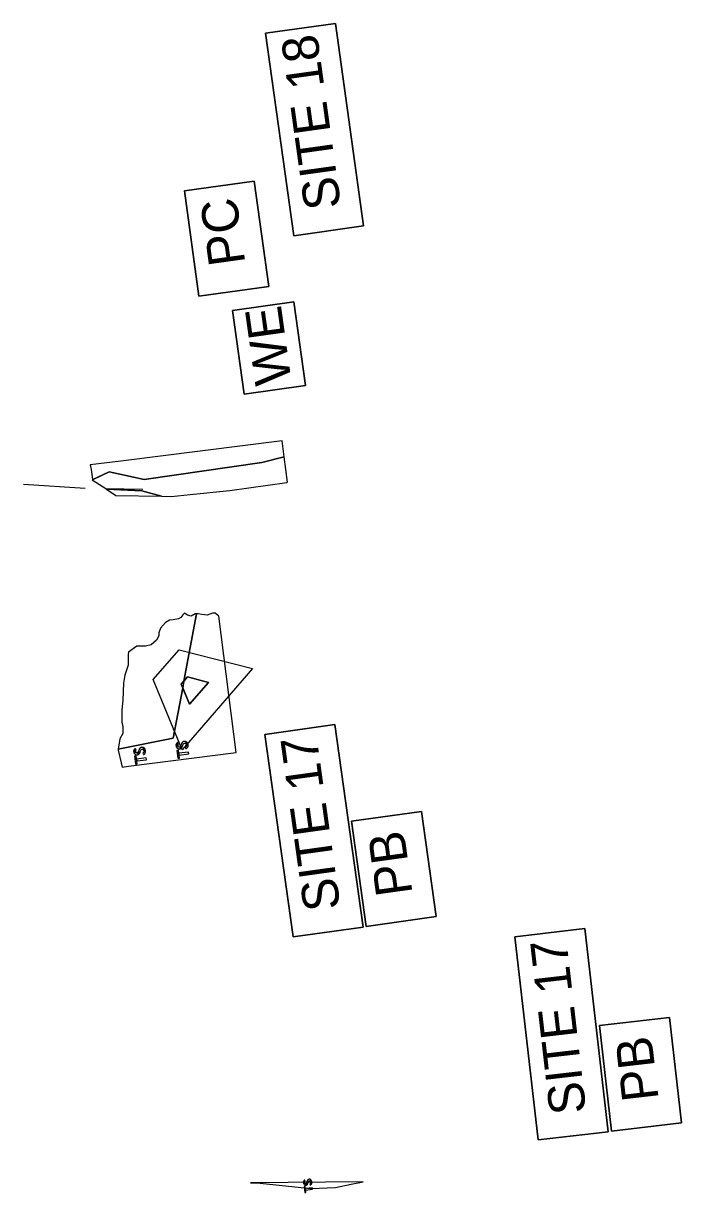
# Model space of a CAD drawing. Extents: x 474218 to 481634, y 484357 to 504997.
# Drawn here: x 478213.3 to 478484.7, y 496625.4 to 497106.9 of the extents above; entities that cross this region are included whole.
import ezdxf

# ---------------------------------------------------------------- set-up
doc = ezdxf.new("R2010")
doc.units = 0
for name, color, linetype in [('Exist Hydro Jurisdictional Stream or Body of Water', 7, 'Continuous'), ('Old_Level_29', 7, 'Continuous'), ('Old_Level_30', 7, 'Continuous'), ('Prop Boundary Clearing Mechanized Hatching CELL', 7, 'Continuous'), ('Prop Earthen Structure Fill In Wetlands Hatching CELL', 7, 'Continuous'), ('Prop Earthen Structure Impacts In Surface Waters Pond Hatching CELL', 7, 'Continuous'), ('Prop Grid Mask', 7, 'Continuous'), ('Scratch_Level_4', 7, 'Continuous'), ('Temp Earthen Structure Impacts In Surface Waters Hatching CELL', 7, 'Continuous')]:
    doc.layers.add(name, color=color, linetype=linetype)

msp = doc.modelspace()

# ---------------------------------------------------------------- linework, layer by layer
at = {"layer": 'Exist Hydro Jurisdictional Stream or Body of Water'}
for points in [[(478285.73, 496994.6), (478279.71, 497037.91), (478308.51, 497041.92), (478314.54, 496998.61)], [(478354.65, 496735.02), (478348.62, 496778.33), (478377.42, 496782.34), (478383.45, 496739.03)], [(478455.76, 496650.73), (478450.76, 496694.17), (478479.65, 496697.5), (478484.66, 496654.06)]]:
    msp.add_lwpolyline(points, close=True, dxfattribs=at)
at = {"layer": 'Old_Level_29'}
for points in [[(478324.77, 497019.47), (478313.16, 497102.9), (478341.97, 497106.91), (478353.58, 497023.48)], [(478324.51, 496730.65), (478312.9, 496814.09), (478341.72, 496818.1), (478353.33, 496734.66)], [(478425.54, 496647.07), (478415.89, 496730.75), (478444.79, 496734.09), (478454.44, 496650.4)]]:
    msp.add_lwpolyline(points, close=True, dxfattribs=at)
at = {"layer": 'Old_Level_30'}
msp.add_lwpolyline([(478304.34, 496954.22), (478299.55, 496988.65), (478324.84, 496992.17), (478329.63, 496957.74)], close=True, dxfattribs=at)
at = {"layer": 'Prop Boundary Clearing Mechanized Hatching CELL'}
for p, q in [((478322.2, 496917.91), (478320.86, 496928.41)), ((478247.68, 496915.04), (478262.17, 496914.35))]:
    msp.add_line(p, q, dxfattribs=at)
for points in [[(478320.86, 496928.41), (478311.66, 496926.12), (478263.19, 496919.03), (478248.75, 496922.25), (478241.67, 496918.9), (478247.68, 496915.04)], [(478282.07, 496912.91), (478298.47, 496914.55), (478321.92, 496917.86), (478322.2, 496917.91)], [(478262.17, 496914.35), (478270.31, 496912.18), (478274.23, 496912.1), (478282.07, 496912.91)]]:
    msp.add_lwpolyline(points, dxfattribs=at)
at = {"layer": 'Prop Earthen Structure Fill In Wetlands Hatching CELL'}
for p, q in [((478262.16, 496914.34), (478247.67, 496915.02)), ((478247.67, 496915.02), (478251.52, 496912.54)), ((478270.31, 496912.18), (478262.16, 496914.34))]:
    msp.add_line(p, q, dxfattribs=at)
msp.add_lwpolyline([(478251.52, 496912.54), (478270.31, 496912.18), (478270.31, 496912.18)], dxfattribs=at)
at = {"layer": 'Prop Earthen Structure Impacts In Surface Waters Pond Hatching CELL'}
for p, q in [((478279.51, 496836.01), (478284.67, 496863.72)), ((478284.67, 496863.72), (478284.22, 496863.68)), ((478279.01, 496833.28), (478279.51, 496836.01)), ((478279.51, 496836.01), (478279.01, 496833.28)), ((478281.03, 496837.75), (478279.51, 496836.01)), ((478289.69, 496835.52), (478281.03, 496837.75)), ((478281.82, 496826.47), (478289.69, 496835.52)), ((478275.15, 496812.55), (478279.01, 496833.28)), ((478279.01, 496833.28), (478281.82, 496826.47)), ((478252.43, 496807.95), (478275.15, 496812.55))]:
    msp.add_line(p, q, dxfattribs=at)
msp.add_lwpolyline([(478284.22, 496863.68), (478282.48, 496862.74), (478280.93, 496863.13), (478279.81, 496863.95), (478279.06, 496863.35), (478278.21, 496862.25), (478277.31, 496861.63), (478275.05, 496861.28), (478273.6, 496861.08), (478271.92, 496860.13), (478269.89, 496857.79), (478269.22, 496855.97), (478269.23, 496854.69), (478268.17, 496852.91), (478265.98, 496850.96), (478263.73, 496850.4), (478261.29, 496850.44), (478260.12, 496850.39), (478256.68, 496847.93), (478256.5, 496846.94), (478256.53, 496842.54), (478255.13, 496838.43), (478254.67, 496835.16), (478254.38, 496828.25), (478253.86, 496824.24), (478253.95, 496819.06), (478254.4, 496817.15), (478254.36, 496814.43), (478253.14, 496812.27), (478252.43, 496807.95)], dxfattribs=at)
at = {"layer": 'Prop Grid Mask'}
for points in [[(478353.58, 497023.48), (478341.97, 497106.91), (478313.16, 497102.9), (478324.77, 497019.47)], [(478314.54, 496998.61), (478308.51, 497041.92), (478279.71, 497037.91), (478285.73, 496994.6)], [(478329.63, 496957.74), (478324.84, 496992.17), (478299.55, 496988.65), (478304.34, 496954.22)], [(478353.33, 496734.66), (478341.72, 496818.1), (478312.9, 496814.09), (478324.51, 496730.65)], [(478383.45, 496739.03), (478377.42, 496782.34), (478348.62, 496778.33), (478354.65, 496735.02)], [(478454.44, 496650.4), (478444.79, 496734.09), (478415.89, 496730.75), (478425.54, 496647.07)], [(478484.66, 496654.06), (478479.65, 496697.5), (478450.76, 496694.17), (478455.76, 496650.73)]]:
    msp.add_lwpolyline(points, close=True, dxfattribs=at)
at = {"layer": 'Scratch_Level_4'}
for p, q in [((478213.34, 496917.2), (478238.77, 496915.45)), ((478247.22, 496915.33), (478262.57, 496915.09)), ((478278.4, 496834.73), (478281.03, 496837.75)), ((478281.03, 496837.75), (478289.69, 496835.52)), ((478289.69, 496835.52), (478281.82, 496826.47)), ((478281.82, 496826.47), (478278.4, 496834.73))]:
    msp.add_line(p, q, dxfattribs=at)
msp.add_lwpolyline([(478278.76, 496807.69), (478266.8, 496836.63), (478277.53, 496848.98), (478307.85, 496841.18)], close=True, dxfattribs=at)
at = {"layer": 'Temp Earthen Structure Impacts In Surface Waters Hatching CELL'}
for p, q in [((478320, 496935.04), (478253.54, 496926.56)), ((478320.85, 496928.41), (478320, 496935.04)), ((478253.54, 496926.56), (478240.89, 496925.1)), ((478241.8, 496919.02), (478241.81, 496918.96)), ((478284.67, 496863.72), (478279.51, 496836.01)), ((478301.11, 496806.61), (478293.95, 496862.73)), ((478279.51, 496836.01), (478281.03, 496837.75)), ((478281.03, 496837.75), (478289.69, 496835.52)), ((478289.69, 496835.52), (478281.82, 496826.47)), ((478279.01, 496833.28), (478275.15, 496812.55)), ((478281.82, 496826.47), (478279.01, 496833.28)), ((478275.15, 496812.55), (478252.43, 496807.95)), ((478256.68, 496800.94), (478301.11, 496806.61)), ((478254.04, 496800.57), (478256.68, 496800.94))]:
    msp.add_line(p, q, dxfattribs=at)
for points in [[(478241.81, 496918.96), (478248.75, 496922.25), (478263.19, 496919.03), (478311.66, 496926.12), (478320.85, 496928.41)], [(478240.89, 496925.1), (478241.22, 496923.15), (478241.8, 496919.02)], [(478293.95, 496862.73), (478292.42, 496864), (478291.24, 496863.98), (478289.14, 496863.15), (478286.92, 496863.45), (478285.38, 496863.78), (478284.67, 496863.72)], [(478252.43, 496807.95), (478252.36, 496807.54), (478253.69, 496802.38), (478254.04, 496800.57)], [(478312.15, 496629.12), (478331.81, 496627.04), (478342.06, 496627.54), (478348.46, 496628.92), (478353.35, 496629.81), (478306.92, 496629.36), (478310.93, 496629.25), (478312.15, 496629.12)]]:
    msp.add_lwpolyline(points, dxfattribs=at)
for points in [[(478259, 496806.4), (478259.02, 496806.34), (478258.88, 496807.5), (478258.88, 496807.48), (478258.86, 496806.89), (478258.86, 496806.89)], [(478260.43, 496805.68), (478260.6, 496805.71), (478260.5, 496806.59), (478260.34, 496806.47), (478260.08, 496806.43), (478260.07, 496806.42), (478260, 496806.44), (478259.83, 496806.49), (478259.76, 496806.55), (478259.67, 496806.63), (478259.63, 496806.67), (478259.62, 496806.7), (478259.58, 496806.81), (478259.52, 496806.96), (478259.37, 496808.25), (478259.29, 496808.21), (478259.09, 496807.97), (478259.04, 496807.92), (478258.88, 496807.5), (478259.02, 496806.34), (478259.26, 496806.02), (478259.32, 496805.93), (478259.57, 496805.79), (478259.66, 496805.74), (478259.7, 496805.71), (478259.74, 496805.7), (478259.74, 496805.69), (478259.78, 496805.69), (478259.86, 496805.68), (478259.92, 496805.67), (478260.1, 496805.64), (478260.16, 496805.63), (478260.18, 496805.63)], [(478259.7, 496807.61), (478259.85, 496807.77), (478259.64, 496808.07), (478259.57, 496808.18), (478259.48, 496808.32), (478259.44, 496808.3), (478259.44, 496808.29), (478259.41, 496808.28), (478259.37, 496808.25), (478259.52, 496806.96), (478259.52, 496807.29), (478259.55, 496807.35), (478259.55, 496807.36), (478259.58, 496807.42), (478259.65, 496807.56)], [(478260.87, 496805.88), (478260.96, 496805.94), (478260.82, 496807.18), (478260.74, 496806.95), (478260.57, 496806.65), (478260.5, 496806.6), (478260.6, 496805.71), (478260.68, 496805.76)], [(478262.97, 496807.63), (478263.05, 496807.35), (478262.9, 496808.65), (478262.85, 496808.68), (478262.84, 496808.68), (478262.83, 496808.68), (478262.73, 496808.73), (478262.69, 496808.74), (478262.66, 496808.74), (478262.52, 496808.75), (478262.46, 496808.76), (478262.42, 496808.76), (478262.23, 496808.78), (478262.13, 496808.76), (478261.87, 496808.7), (478261.75, 496808.67), (478261.67, 496808.61), (478261.5, 496808.49), (478261.5, 496808.49), (478261.37, 496808.39), (478261.29, 496808.27), (478261.1, 496807.95), (478261.06, 496807.85), (478260.89, 496807.41), (478260.82, 496807.18), (478260.96, 496805.94), (478261.05, 496806.04), (478261.24, 496806.28), (478261.28, 496806.37), (478261.46, 496806.78), (478261.53, 496806.98), (478261.64, 496807.28), (478261.78, 496807.65), (478261.86, 496807.75), (478261.96, 496807.88), (478262.21, 496807.99), (478262.32, 496807.99), (478262.5, 496807.99), (478262.55, 496807.97), (478262.62, 496807.95), (478262.76, 496807.89), (478262.79, 496807.85), (478262.84, 496807.8), (478262.95, 496807.67), (478262.96, 496807.65)], [(478263.72, 496806.74), (478263.75, 496807.39), (478263.57, 496808.04), (478263.57, 496808.04), (478263.23, 496808.46), (478263.19, 496808.51), (478262.9, 496808.65), (478263.05, 496807.35), (478263.04, 496806.99), (478263.04, 496806.99), (478263.03, 496806.96), (478262.96, 496806.77), (478262.93, 496806.7), (478262.9, 496806.67), (478262.78, 496806.54), (478262.72, 496806.49), (478262.68, 496806.46), (478262.52, 496806.38), (478262.73, 496806.02), (478262.79, 496805.93), (478262.86, 496805.81), (478262.99, 496805.87), (478263.02, 496805.88), (478263.06, 496805.89), (478263.15, 496805.94), (478263.16, 496805.95), (478263.16, 496805.95), (478263.21, 496805.99), (478263.45, 496806.21), (478263.48, 496806.24), (478263.72, 496806.73)], [(478276.48, 496808.83), (478276.5, 496808.77), (478276.36, 496809.93), (478276.36, 496809.91), (478276.34, 496809.33), (478276.34, 496809.32)], [(478277.91, 496808.11), (478278.08, 496808.15), (478277.98, 496809.03), (478277.82, 496808.91), (478277.56, 496808.86), (478277.55, 496808.86), (478277.48, 496808.87), (478277.31, 496808.92), (478277.24, 496808.98), (478277.15, 496809.06), (478277.11, 496809.1), (478277.1, 496809.13), (478277.06, 496809.25), (478277, 496809.39), (478276.85, 496810.69), (478276.77, 496810.64), (478276.57, 496810.4), (478276.52, 496810.35), (478276.36, 496809.93), (478276.5, 496808.77), (478276.74, 496808.45), (478276.8, 496808.37), (478277.05, 496808.22), (478277.14, 496808.17), (478277.18, 496808.15), (478277.21, 496808.13), (478277.22, 496808.13), (478277.26, 496808.12), (478277.34, 496808.11), (478277.4, 496808.1), (478277.57, 496808.08), (478277.64, 496808.07), (478277.66, 496808.06)], [(478277.03, 496804.28), (478277.68, 496804.35), (478277.31, 496807.57), (478276.66, 496807.5)], [(478277.18, 496810.04), (478277.33, 496810.2), (478277.12, 496810.51), (478277.05, 496810.61), (478276.96, 496810.75), (478276.92, 496810.73), (478276.92, 496810.73), (478276.89, 496810.71), (478276.85, 496810.69), (478277, 496809.39), (478277, 496809.73), (478277.02, 496809.78), (478277.03, 496809.79), (478277.06, 496809.86), (478277.12, 496809.99)], [(478277.54, 496805.58), (478281.54, 496806.05), (478281.45, 496806.8), (478277.45, 496806.34)], [(478278.35, 496808.31), (478278.44, 496808.37), (478278.3, 496809.61), (478278.22, 496809.38), (478278.05, 496809.08), (478277.98, 496809.03), (478278.08, 496808.14), (478278.16, 496808.19)], [(478280.45, 496810.07), (478280.53, 496809.78), (478280.38, 496811.08), (478280.33, 496811.11), (478280.32, 496811.11), (478280.31, 496811.12), (478280.21, 496811.17), (478280.17, 496811.17), (478280.14, 496811.17), (478280, 496811.19), (478279.94, 496811.19), (478279.89, 496811.2), (478279.71, 496811.21), (478279.61, 496811.19), (478279.35, 496811.13), (478279.23, 496811.11), (478279.15, 496811.04), (478278.98, 496810.92), (478278.98, 496810.92), (478278.85, 496810.83), (478278.77, 496810.7), (478278.58, 496810.38), (478278.54, 496810.28), (478278.37, 496809.84), (478278.3, 496809.61), (478278.44, 496808.37), (478278.53, 496808.48), (478278.72, 496808.72), (478278.76, 496808.81), (478278.94, 496809.22), (478279.01, 496809.41), (478279.12, 496809.72), (478279.26, 496810.08), (478279.34, 496810.18), (478279.44, 496810.31), (478279.69, 496810.42), (478279.8, 496810.42), (478279.98, 496810.43), (478280.03, 496810.41), (478280.1, 496810.38), (478280.24, 496810.33), (478280.27, 496810.29), (478280.32, 496810.23), (478280.43, 496810.1), (478280.44, 496810.08)], [(478281.2, 496809.18), (478281.23, 496809.83), (478281.05, 496810.47), (478281.05, 496810.48), (478280.71, 496810.89), (478280.67, 496810.94), (478280.38, 496811.08), (478280.53, 496809.78), (478280.52, 496809.42), (478280.52, 496809.42), (478280.51, 496809.39), (478280.44, 496809.2), (478280.41, 496809.13), (478280.38, 496809.1), (478280.26, 496808.97), (478280.2, 496808.92), (478280.16, 496808.9), (478279.99, 496808.81), (478280.21, 496808.45), (478280.27, 496808.36), (478280.34, 496808.24), (478280.47, 496808.3), (478280.5, 496808.31), (478280.54, 496808.33), (478280.63, 496808.37), (478280.64, 496808.38), (478280.64, 496808.38), (478280.69, 496808.42), (478280.93, 496808.64), (478280.96, 496808.67), (478281.2, 496809.17)], [(478259.55, 496801.84), (478260.2, 496801.92), (478259.83, 496805.14), (478259.18, 496805.06)], [(478260.06, 496803.15), (478264.06, 496803.61), (478263.97, 496804.37), (478259.97, 496803.91)], [(478328.91, 496629.02), (478328.92, 496628.98), (478328.81, 496629.9), (478328.81, 496629.89), (478328.8, 496629.42), (478328.8, 496629.42)], [(478329.93, 496628.43), (478330.05, 496628.46), (478329.97, 496629.16), (478329.86, 496629.07), (478329.67, 496629.03), (478329.66, 496629.03), (478329.62, 496629.05), (478329.49, 496629.08), (478329.44, 496629.13), (478329.38, 496629.2), (478329.35, 496629.23), (478329.34, 496629.26), (478329.31, 496629.35), (478329.27, 496629.47), (478329.15, 496630.5), (478329.1, 496630.47), (478328.95, 496630.28), (478328.92, 496630.24), (478328.81, 496629.9), (478328.92, 496628.98), (478329.09, 496628.72), (478329.14, 496628.65), (478329.32, 496628.53), (478329.38, 496628.49), (478329.41, 496628.47), (478329.43, 496628.45), (478329.44, 496628.45), (478329.47, 496628.45), (478329.53, 496628.44), (478329.57, 496628.43), (478329.69, 496628.41), (478329.74, 496628.4), (478329.75, 496628.4)], [(478329.39, 496629.99), (478329.49, 496630.11), (478329.34, 496630.36), (478329.29, 496630.44), (478329.22, 496630.56), (478329.2, 496630.54), (478329.19, 496630.53), (478329.18, 496630.52), (478329.15, 496630.5), (478329.27, 496629.47), (478329.27, 496629.73), (478329.28, 496629.78), (478329.29, 496629.79), (478329.31, 496629.84), (478329.35, 496629.95)], [(478330.23, 496628.59), (478330.3, 496628.63), (478330.19, 496629.63), (478330.14, 496629.44), (478330.02, 496629.21), (478329.97, 496629.16), (478330.05, 496628.46), (478330.1, 496628.49)], [(478331.7, 496629.97), (478331.76, 496629.74), (478331.64, 496630.78), (478331.6, 496630.8), (478331.6, 496630.81), (478331.59, 496630.81), (478331.52, 496630.85), (478331.49, 496630.85), (478331.47, 496630.86), (478331.37, 496630.87), (478331.33, 496630.87), (478331.3, 496630.88), (478331.17, 496630.89), (478331.09, 496630.88), (478330.91, 496630.83), (478330.83, 496630.81), (478330.77, 496630.76), (478330.65, 496630.67), (478330.65, 496630.67), (478330.56, 496630.59), (478330.51, 496630.49), (478330.37, 496630.24), (478330.35, 496630.16), (478330.23, 496629.81), (478330.19, 496629.63), (478330.3, 496628.63), (478330.36, 496628.72), (478330.49, 496628.91), (478330.52, 496628.98), (478330.65, 496629.31), (478330.69, 496629.46), (478330.77, 496629.7), (478330.86, 496629.99), (478330.92, 496630.07), (478330.99, 496630.17), (478331.16, 496630.26), (478331.24, 496630.26), (478331.37, 496630.26), (478331.4, 496630.25), (478331.45, 496630.23), (478331.55, 496630.18), (478331.58, 496630.15), (478331.61, 496630.1), (478331.69, 496630), (478331.7, 496629.98)], [(478332.24, 496629.25), (478332.25, 496629.77), (478332.12, 496630.29), (478332.12, 496630.29), (478331.88, 496630.62), (478331.85, 496630.67), (478331.64, 496630.78), (478331.76, 496629.74), (478331.76, 496629.45), (478331.76, 496629.45), (478331.75, 496629.43), (478331.7, 496629.28), (478331.68, 496629.22), (478331.66, 496629.2), (478331.58, 496629.1), (478331.54, 496629.05), (478331.51, 496629.04), (478331.39, 496628.97), (478331.55, 496628.68), (478331.59, 496628.6), (478331.65, 496628.51), (478331.74, 496628.56), (478331.76, 496628.56), (478331.78, 496628.58), (478331.85, 496628.61), (478331.85, 496628.62), (478331.86, 496628.62), (478331.89, 496628.65), (478332.06, 496628.83), (478332.08, 496628.85), (478332.24, 496629.24)], [(478329.35, 496625.37), (478329.8, 496625.43), (478329.51, 496628.01), (478329.05, 496627.95)], [(478329.69, 496626.42), (478332.52, 496626.74), (478332.45, 496627.35), (478329.62, 496627.02)]]:
    msp.add_lwpolyline(points, close=True, dxfattribs=at)

# ---------------------------------------------------------------- texts
at = {"layer": 'Exist Hydro Jurisdictional Stream or Body of Water'}
for s, rotation, p in [('PC', 97.923, (478304.87, 497008.16)), ('PB', 97.923, (478373.78, 496748.58)), ('PB', 96.5776, (478475.21, 496663.83))]:
    msp.add_text(s, height=15, rotation=rotation, dxfattribs=at).set_placement(p)
at = {"layer": 'Old_Level_29'}
for s, rotation, p in [('SITE 18', 97.923, (478344.32, 497031.31)), ('SITE 17', 97.923, (478344.07, 496742.5)), ('SITE 17', 96.5776, (478445.37, 496658.45))]:
    msp.add_text(s, height=15, rotation=rotation, dxfattribs=at).set_placement(p)
at = {"layer": 'Old_Level_30'}
msp.add_text('WE', height=15, rotation=97.923, dxfattribs=at).set_placement((478323.91, 496959.2))

doc.saveas('drawing.dxf')
